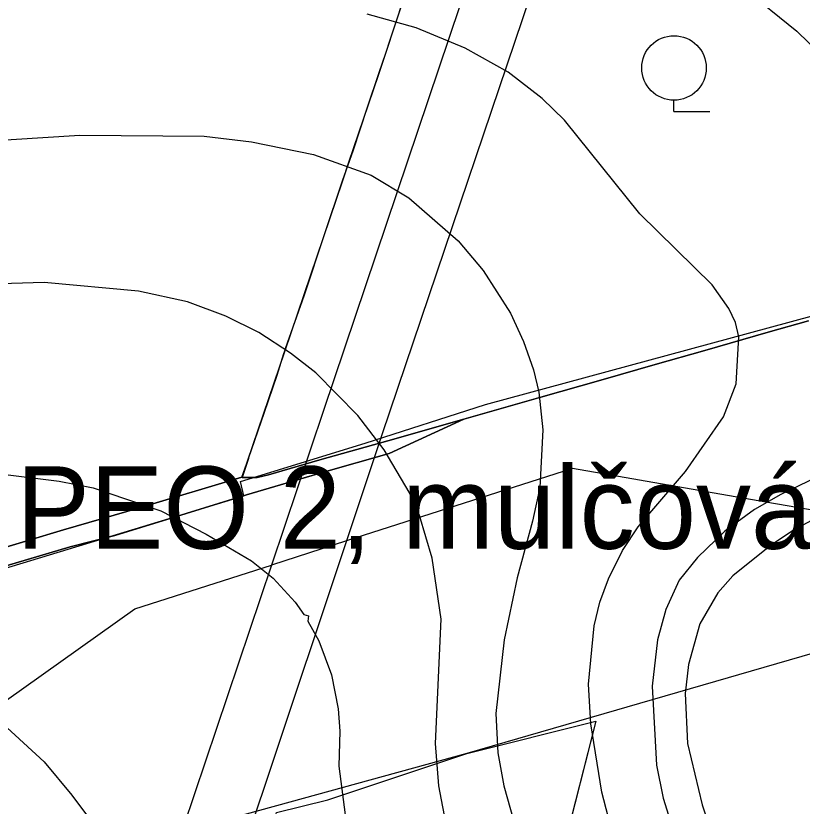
# Model space of a CAD drawing. Extents: x -662620 to -656370, y -1067090 to -1062990.
# Drawn here: x -658244 to -658005.3, y -1065447 to -1065207 of the extents above; entities that cross this region are included whole.
import ezdxf

# ---------------------------------------------------------------- set-up
doc = ezdxf.new("R2010")
doc.units = 0
for name, color, linetype in [('Agrotechnicka_opatreni_hrazkovani_a_dulkovani__mulcovani', 7, 'Continuous'), ('ELEK__VEDENÍ_VN_-_NADZEMNÍ', 7, 'Continuous'), ('ELEK__VEDENÍ_VVN_-_NADZEMNÍ', 7, 'Continuous'), ('OBVOD_PÚ', 7, 'Continuous'), ('ORNÁ_PŮDA_-_STÁVAJÍCÍ', 7, 'Continuous'), ('OSTATNÍ_PLOCHA_-_STÁVAJÍCÍ', 7, 'Continuous'), ('OVOCNÝ_SAD_-_NAVRŽENÝ', 7, 'Continuous'), ('OVOCNÝ_SAD_-_STÁVAJÍCÍ', 7, 'Continuous'), ('OVOCNÝ_SAD_-_ZNAČKA', 7, 'Continuous'), ('VRSTEVNICE_ZDŮRAZNĚNÁ', 7, 'Continuous'), ('VRSTEVNICE_ZÁKLADNÍ', 7, 'Continuous')]:
    doc.layers.add(name, color=color, linetype=linetype)

msp = doc.modelspace()

# ---------------------------------------------------------------- linework, layer by layer
at = {"layer": 'Agrotechnicka_opatreni_hrazkovani_a_dulkovani__mulcovani'}
msp.add_lwpolyline([(-658442.44, -1065523.3), (-658443.3, -1065431.9), (-658351.8, -1065406.5), (-658174.8, -1065352.7), (-658175.8, -1065348.4), (-658137.9, -1065336.7), (-658101.39, -1065325.05), (-657977.61, -1065291.39), (-657955.7, -1065285), (-657886.54, -1065253.17), (-657902.2, -1065289.3), (-657944.34, -1065374.26), (-657952.2, -1065387.5), (-657958.74, -1065388.45), (-657979.2, -1065393.9), (-658107.1, -1065431), (-658344.5, -1065496.2)], close=True, dxfattribs=at)
at = {"layer": 'ELEK__VEDENÍ_VN_-_NADZEMNÍ'}
for points in [[(-657905.04, -1065373.88), (-657939.31, -1065367.86), (-658016.35, -1065354.65), (-658074.98, -1065344.41), (-658143.6, -1065366.43)], [(-658431.73, -1065546.01), (-658402.37, -1065525.35), (-658362.82, -1065497.28), (-658280.56, -1065438.78), (-658207.8, -1065387.04), (-658166.37, -1065373.74)]]:
    msp.add_lwpolyline(points, dxfattribs=at)
at = {"layer": 'ELEK__VEDENÍ_VVN_-_NADZEMNÍ'}
for points in [[(-658053.43, -1065038.07), (-658074.34, -1065100.23), (-658150.55, -1065326.78), (-658166.37, -1065373.74)], [(-658037.26, -1065051.34), (-658078.35, -1065172.84), (-658132.86, -1065334.22), (-658143.6, -1065366.43)], [(-658143.6, -1065366.43), (-658167.84, -1065439.13), (-658202.48, -1065541.95), (-658241.62, -1065658.23), (-658283.03, -1065781.93), (-658282.55, -1065909.7), (-658281.02, -1066039.46), (-658280.08, -1066204), (-658279.27, -1066280.92)], [(-658143.6, -1065366.43), (-658166.37, -1065373.74)], [(-658166.37, -1065373.74), (-658226.48, -1065552.24), (-658303.49, -1065780.98), (-658301.72, -1066029.74), (-658299.99, -1066275.27)]]:
    msp.add_lwpolyline(points, dxfattribs=at)
at = {"layer": 'OBVOD_PÚ'}
for points in [[(-658122.81, -1065191.08), (-658128.25, -1065207.74)], [(-658128.25, -1065207.74), (-658133.86, -1065224.83)], [(-658133.86, -1065224.83), (-658143.06, -1065251.84)], [(-658143.06, -1065251.84), (-658144.85, -1065257.14)], [(-658144.85, -1065257.14), (-658162.41, -1065309.04)], [(-658162.41, -1065309.04), (-658175.32, -1065347.1)], [(-658175.32, -1065347.1), (-658206.44, -1065356.34)], [(-658206.44, -1065356.34), (-658229.45, -1065363.09)], [(-658229.45, -1065363.09), (-658252.46, -1065369.9)]]:
    msp.add_lwpolyline(points, dxfattribs=at)
at = {"layer": 'ORNÁ_PŮDA_-_STÁVAJÍCÍ'}
for p, q in [((-658015.69, -1065303.03), (-658003.41, -1065299.59)), ((-658034.91, -1065308.59), (-658015.69, -1065303.03)), ((-658049.97, -1065312.82), (-658034.91, -1065308.59)), ((-658065.75, -1065317.44), (-658049.97, -1065312.82)), ((-658085.31, -1065323), (-658065.75, -1065317.44)), ((-658107.97, -1065329.48), (-658085.31, -1065323)), ((-658130.7, -1065339.84), (-658107.97, -1065329.48)), ((-658150.63, -1065345.58), (-658130.7, -1065339.84)), ((-658173.96, -1065352.39), (-658150.63, -1065345.58)), ((-658200.78, -1065360.71), (-658173.96, -1065352.39)), ((-658213.95, -1065364.73), (-658200.78, -1065360.71)), ((-658227.45, -1065368.23), (-658213.95, -1065364.73)), ((-658246.87, -1065373.99), (-658227.45, -1065368.23))]:
    msp.add_line(p, q, dxfattribs=at)
msp.add_lwpolyline([(-658246.87, -1065373.99), (-658227.45, -1065368.23), (-658213.95, -1065364.73), (-658200.78, -1065360.71), (-658173.96, -1065352.39), (-658150.63, -1065345.58), (-658130.7, -1065339.84), (-658107.97, -1065329.48), (-658085.31, -1065323), (-658065.75, -1065317.44), (-658049.97, -1065312.82), (-658034.91, -1065308.59), (-658015.69, -1065303.03), (-658003.41, -1065299.59)], dxfattribs=at)
at = {"layer": 'OSTATNÍ_PLOCHA_-_STÁVAJÍCÍ'}
for p, q in [((-658131.1, -1065335.99), (-658107.97, -1065329.48)), ((-658131.1, -1065335.99), (-658107.97, -1065329.48)), ((-658107.97, -1065329.48), (-658130.7, -1065339.84)), ((-658107.97, -1065329.48), (-658130.7, -1065339.84)), ((-658151.72, -1065341.81), (-658131.1, -1065335.99)), ((-658151.72, -1065341.81), (-658131.1, -1065335.99)), ((-658130.7, -1065339.84), (-658150.63, -1065345.58)), ((-658130.7, -1065339.84), (-658150.63, -1065345.58)), ((-658175.32, -1065347.1), (-658173.38, -1065341.37)), ((-658175.32, -1065347.1), (-658173.38, -1065341.37)), ((-658173.37, -1065341.37), (-658175.29, -1065347.12)), ((-658173.37, -1065341.37), (-658175.29, -1065347.12)), ((-658173.38, -1065341.37), (-658173.37, -1065341.37)), ((-658173.38, -1065341.37), (-658173.37, -1065341.37)), ((-658167.27, -1065346.39), (-658151.72, -1065341.81)), ((-658167.27, -1065346.39), (-658151.72, -1065341.81)), ((-658206.44, -1065356.34), (-658175.32, -1065347.1)), ((-658206.44, -1065356.34), (-658175.32, -1065347.1)), ((-658175.29, -1065347.12), (-658170.74, -1065347.17)), ((-658175.29, -1065347.12), (-658170.74, -1065347.17)), ((-658150.63, -1065345.58), (-658173.96, -1065352.39)), ((-658150.63, -1065345.58), (-658173.96, -1065352.39)), ((-658170.74, -1065347.17), (-658167.27, -1065346.39)), ((-658170.74, -1065347.17), (-658167.27, -1065346.39)), ((-658173.96, -1065352.39), (-658200.78, -1065360.71)), ((-658173.96, -1065352.39), (-658200.78, -1065360.71)), ((-658229.45, -1065363.09), (-658206.44, -1065356.34)), ((-658229.45, -1065363.09), (-658206.44, -1065356.34)), ((-658200.78, -1065360.71), (-658213.95, -1065364.73)), ((-658200.78, -1065360.71), (-658213.95, -1065364.73)), ((-658252.46, -1065369.9), (-658229.45, -1065363.09)), ((-658252.46, -1065369.9), (-658229.45, -1065363.09)), ((-658213.95, -1065364.73), (-658227.45, -1065368.23)), ((-658213.95, -1065364.73), (-658227.45, -1065368.23)), ((-658227.45, -1065368.23), (-658246.87, -1065373.99)), ((-658227.45, -1065368.23), (-658246.87, -1065373.99))]:
    msp.add_line(p, q, dxfattribs=at)
msp.add_lwpolyline([(-658252.46, -1065369.9), (-658229.45, -1065363.09), (-658206.44, -1065356.34), (-658175.32, -1065347.1), (-658173.38, -1065341.37), (-658173.37, -1065341.37), (-658175.29, -1065347.12), (-658170.74, -1065347.17), (-658167.27, -1065346.39), (-658151.72, -1065341.81), (-658131.1, -1065335.99), (-658107.97, -1065329.48), (-658130.7, -1065339.84), (-658150.63, -1065345.58), (-658173.96, -1065352.39), (-658200.78, -1065360.71), (-658213.95, -1065364.73), (-658227.45, -1065368.23), (-658246.87, -1065373.99)], dxfattribs=at)
msp.add_lwpolyline([(-658252.46, -1065369.9), (-658229.45, -1065363.09), (-658206.44, -1065356.34), (-658175.32, -1065347.1), (-658173.38, -1065341.37), (-658173.37, -1065341.37), (-658175.29, -1065347.12), (-658170.74, -1065347.17), (-658167.27, -1065346.39), (-658151.72, -1065341.81), (-658131.1, -1065335.99), (-658107.97, -1065329.48), (-658130.7, -1065339.84), (-658150.63, -1065345.58), (-658173.96, -1065352.39), (-658200.78, -1065360.71), (-658213.95, -1065364.73), (-658227.45, -1065368.23), (-658246.87, -1065373.99)], dxfattribs=at)
at = {"layer": 'OVOCNÝ_SAD_-_NAVRŽENÝ'}
for p, q in [((-658107.1, -1065431), (-658067.9, -1065421.1)), ((-658067.9, -1065421.1), (-658088.9, -1065503.2)), ((-658149.3, -1065445), (-658107.1, -1065431)), ((-658164.8, -1065448.9), (-658149.3, -1065445))]:
    msp.add_line(p, q, dxfattribs=at)
msp.add_lwpolyline([(-658221.5, -1065701.5), (-658165.55, -1065451.1), (-658164.91, -1065449.23), (-658164.8, -1065448.9), (-658149.3, -1065445), (-658107.1, -1065431), (-658067.9, -1065421.1), (-658088.9, -1065503.2), (-658064.4, -1065506.7), (-658074.9, -1065548.6), (-658009.6, -1065541.5), (-657999.43, -1065500.58)], dxfattribs=at)
at = {"layer": 'OVOCNÝ_SAD_-_STÁVAJÍCÍ'}
for p, q in [((-658131.66, -1065218.34), (-658126.03, -1065201.07)), ((-658133.65, -1065224.19), (-658131.66, -1065218.34)), ((-658137.14, -1065234.45), (-658133.86, -1065224.83)), ((-658133.86, -1065224.83), (-658133.65, -1065224.19)), ((-658137.22, -1065234.7), (-658137.14, -1065234.45)), ((-658141.47, -1065247.67), (-658137.22, -1065234.7)), ((-658144.86, -1065257.14), (-658141.47, -1065247.67)), ((-658150.17, -1065273.09), (-658144.86, -1065257.14)), ((-658156.33, -1065291.68), (-658150.17, -1065273.09)), ((-658162.07, -1065308.03), (-658156.33, -1065291.68)), ((-658003.41, -1065299.59), (-658015.69, -1065303.03)), ((-658015.69, -1065303.03), (-658034.91, -1065308.59)), ((-658162.41, -1065309.04), (-658162.07, -1065308.03)), ((-658034.91, -1065308.59), (-658049.97, -1065312.82)), ((-658164.63, -1065316.15), (-658162.57, -1065309.52)), ((-658162.57, -1065309.52), (-658162.41, -1065309.04)), ((-658049.97, -1065312.82), (-658065.75, -1065317.44)), ((-658168.53, -1065327.3), (-658164.63, -1065316.15)), ((-658065.75, -1065317.44), (-658085.31, -1065323)), ((-658085.31, -1065323), (-658107.97, -1065329.48)), ((-658173.37, -1065341.37), (-658168.53, -1065327.3)), ((-658107.97, -1065329.48), (-658131.1, -1065335.99)), ((-658131.1, -1065335.99), (-658151.72, -1065341.81)), ((-658175.29, -1065347.12), (-658173.37, -1065341.37)), ((-658151.72, -1065341.81), (-658167.27, -1065346.39)), ((-658170.74, -1065347.17), (-658175.29, -1065347.12)), ((-658167.27, -1065346.39), (-658170.74, -1065347.17))]:
    msp.add_line(p, q, dxfattribs=at)
msp.add_lwpolyline([(-658003.41, -1065299.59), (-658015.69, -1065303.03), (-658034.91, -1065308.59), (-658049.97, -1065312.82), (-658065.75, -1065317.44), (-658085.31, -1065323), (-658107.97, -1065329.48), (-658131.1, -1065335.99), (-658151.72, -1065341.81), (-658167.27, -1065346.39), (-658170.74, -1065347.17), (-658175.29, -1065347.12), (-658173.37, -1065341.37), (-658168.53, -1065327.3), (-658164.63, -1065316.15), (-658162.57, -1065309.52), (-658162.41, -1065309.04), (-658162.07, -1065308.03), (-658156.33, -1065291.68), (-658150.17, -1065273.09), (-658144.86, -1065257.14), (-658141.47, -1065247.67), (-658137.22, -1065234.7), (-658137.14, -1065234.45), (-658133.86, -1065224.83), (-658133.65, -1065224.19), (-658131.66, -1065218.34), (-658126.03, -1065201.07)], dxfattribs=at)
at = {"layer": 'OVOCNÝ_SAD_-_ZNAČKA'}
for points in [[(-658044.22, -1065236.08), (-658044.22, -1065232.62)], [(-658044.22, -1065236.08), (-658033.38, -1065236.08)]]:
    msp.add_lwpolyline(points, dxfattribs=at)
msp.add_circle((-658044.22, -1065222.83), 9.79, dxfattribs=at)
at = {"layer": 'VRSTEVNICE_ZDŮRAZNĚNÁ'}
for points in [[(-658456.04, -1065403.49), (-658411.02, -1065382.05), (-658399.15, -1065377.33), (-658379.14, -1065370.9), (-658333.69, -1065354.6), (-658316.54, -1065350.46), (-658295.1, -1065347.46), (-658247.93, -1065346.17), (-658230.78, -1065348.32), (-658220.49, -1065350.32), (-658199.9, -1065357.32), (-658186.18, -1065364.32), (-658172.46, -1065372.47), (-658165.89, -1065377.76), (-658159.17, -1065385.05), (-658156.6, -1065388.77), (-658155.17, -1065389.19), (-658155.31, -1065390.77), (-658152.02, -1065396.77), (-658148.16, -1065407.06), (-658146.16, -1065417.35), (-658145.59, -1065424.21), (-658145.88, -1065434.79), (-658143.73, -1065451.94)], [(-657980.36, -1065348.32), (-658007.8, -1065363.04), (-658014.66, -1065367.61), (-658026.38, -1065377.05), (-658030.96, -1065382.19), (-658036.39, -1065391.62), (-658039.82, -1065403.92), (-658040.82, -1065412.78), (-658040.1, -1065427.93), (-658035.67, -1065446.51), (-658030.67, -1065461.38), (-658024.53, -1065476.24), (-658013.09, -1065498.54), (-657976.5, -1065554.85)]]:
    msp.add_lwpolyline(points, dxfattribs=at)
at = {"layer": 'VRSTEVNICE_ZÁKLADNÍ'}
for points in [[(-658023.24, -1065198.38), (-658006.94, -1065211.67), (-657995.8, -1065222.53)], [(-658023.24, -1065198.38), (-658006.94, -1065211.67), (-657995.8, -1065222.53)], [(-658060.4, -1065464.81), (-658066.12, -1065442.65), (-658069.41, -1065421.93), (-658070.12, -1065409.92), (-658068.41, -1065392.2), (-658066.69, -1065385.05), (-658064.12, -1065377.9), (-658059.83, -1065369.33), (-658055.11, -1065362.18), (-658040.68, -1065345.31), (-658029.24, -1065328.73), (-658025.38, -1065318.73), (-658024.53, -1065304.44), (-658025.53, -1065300.15), (-658027.53, -1065295.86), (-658032.67, -1065288.71), (-658054.54, -1065267.13), (-658077.41, -1065238.69), (-658084.27, -1065232.11), (-658094.56, -1065224.11), (-658107.57, -1065216.82), (-658122.43, -1065210.67), (-658137.3, -1065206.53)], [(-658060.4, -1065464.81), (-658066.12, -1065442.65), (-658069.41, -1065421.93), (-658070.12, -1065409.92), (-658068.41, -1065392.2), (-658066.69, -1065385.05), (-658064.12, -1065377.9), (-658059.83, -1065369.33), (-658055.11, -1065362.18), (-658040.68, -1065345.31), (-658029.24, -1065328.73), (-658025.38, -1065318.73), (-658024.53, -1065304.44), (-658025.53, -1065300.15), (-658027.53, -1065295.86), (-658032.67, -1065288.71), (-658054.54, -1065267.13), (-658077.41, -1065238.69), (-658084.27, -1065232.11), (-658094.56, -1065224.11), (-658107.57, -1065216.82), (-658122.43, -1065210.67), (-658137.3, -1065206.53)], [(-658283.95, -1065246.98), (-658224.49, -1065243.26), (-658186.75, -1065243.55), (-658172.46, -1065245.26), (-658153.64, -1065249.16), (-658136.16, -1065255.41), (-658124.72, -1065262.27), (-658109.71, -1065275.28), (-658102.14, -1065284.28), (-658093.85, -1065297.29), (-658089.85, -1065305.86), (-658086.84, -1065314.44), (-658085.27, -1065321.3), (-658083.99, -1065332.74), (-658084.98, -1065350.17), (-658087.13, -1065360.47), (-658091.85, -1065377.62), (-658095.71, -1065396.48), (-658098.28, -1065418.78), (-658097.71, -1065430.79), (-658095.85, -1065440.79), (-658091.85, -1065455.09)], [(-658283.95, -1065246.98), (-658224.49, -1065243.26), (-658186.75, -1065243.55), (-658172.46, -1065245.26), (-658153.64, -1065249.16), (-658136.16, -1065255.41), (-658124.72, -1065262.27), (-658109.71, -1065275.28), (-658102.14, -1065284.28), (-658093.85, -1065297.29), (-658089.85, -1065305.86), (-658086.84, -1065314.44), (-658085.27, -1065321.3), (-658083.99, -1065332.74), (-658084.98, -1065350.17), (-658087.13, -1065360.47), (-658091.85, -1065377.62), (-658095.71, -1065396.48), (-658098.28, -1065418.78), (-658097.71, -1065430.79), (-658095.85, -1065440.79), (-658091.85, -1065455.09)], [(-658110.14, -1065469.38), (-658115.57, -1065440.79), (-658116.57, -1065427.93), (-658114.86, -1065390.2), (-658117.57, -1065371.61), (-658121.43, -1065358.75), (-658124.58, -1065351.6), (-658132.15, -1065338.74), (-658140.16, -1065328.31), (-658152.88, -1065315.44), (-658160.6, -1065309.44), (-658170.17, -1065303.15), (-658180.18, -1065298.15), (-658191.9, -1065293.86), (-658206.76, -1065290.57), (-658235.35, -1065288), (-658265.08, -1065288.86), (-658287.95, -1065291.86), (-658303.96, -1065296.43), (-658333.69, -1065308.44), (-658361.13, -1065318.16), (-658396.29, -1065329.16), (-658477.76, -1065352.46)], [(-658110.14, -1065469.38), (-658115.57, -1065440.79), (-658116.57, -1065427.93), (-658114.86, -1065390.2), (-658117.57, -1065371.61), (-658121.43, -1065358.75), (-658124.58, -1065351.6), (-658132.15, -1065338.74), (-658140.16, -1065328.31), (-658152.88, -1065315.44), (-658160.6, -1065309.44), (-658170.17, -1065303.15), (-658180.18, -1065298.15), (-658191.9, -1065293.86), (-658206.76, -1065290.57), (-658235.35, -1065288), (-658265.08, -1065288.86), (-658287.95, -1065291.86), (-658303.96, -1065296.43), (-658333.69, -1065308.44), (-658361.13, -1065318.16), (-658396.29, -1065329.16), (-658477.76, -1065352.46)], [(-657989.79, -1065341.74), (-658011.8, -1065352.32), (-658019.81, -1065356.89), (-658028.81, -1065363.47), (-658037.1, -1065371.47), (-658042.68, -1065378.33), (-658046.68, -1065387.19), (-658049.25, -1065396.48), (-658050.82, -1065410.49), (-658049.54, -1065434.5), (-658047.54, -1065444.51), (-658041.25, -1065464.52), (-658035.53, -1065478.53), (-658005.23, -1065539.7)], [(-657989.79, -1065341.74), (-658011.8, -1065352.32), (-658019.81, -1065356.89), (-658028.81, -1065363.47), (-658037.1, -1065371.47), (-658042.68, -1065378.33), (-658046.68, -1065387.19), (-658049.25, -1065396.48), (-658050.82, -1065410.49), (-658049.54, -1065434.5), (-658047.54, -1065444.51), (-658041.25, -1065464.52), (-658035.53, -1065478.53), (-658005.23, -1065539.7)], [(-658451.75, -1065447.37), (-658425.17, -1065436.36), (-658367.42, -1065415.35), (-658351.41, -1065411.06), (-658339.41, -1065408.92), (-658329.4, -1065408.06), (-658302.53, -1065408.49), (-658268.51, -1065413.35), (-658258.22, -1065415.92), (-658247.93, -1065421.93), (-658235.35, -1065433.5), (-658226.92, -1065443.65), (-658213.34, -1065461.95), (-658197.9, -1065486.53), (-658193.47, -1065495.11), (-658188.76, -1065506.54), (-658182.18, -1065527.98), (-658177.46, -1065552.28), (-658173.18, -1065590.87), (-658172.32, -1065603.74), (-658172.32, -1065619.46), (-658173.46, -1065638.04), (-658177.61, -1065666.63), (-658184.75, -1065698.07)], [(-658451.75, -1065447.37), (-658425.17, -1065436.36), (-658367.42, -1065415.35), (-658351.41, -1065411.06), (-658339.41, -1065408.92), (-658329.4, -1065408.06), (-658302.53, -1065408.49), (-658268.51, -1065413.35), (-658258.22, -1065415.92), (-658247.93, -1065421.93), (-658235.35, -1065433.5), (-658226.92, -1065443.65), (-658213.34, -1065461.95), (-658197.9, -1065486.53), (-658193.47, -1065495.11), (-658188.76, -1065506.54), (-658182.18, -1065527.98), (-658177.46, -1065552.28), (-658173.18, -1065590.87), (-658172.32, -1065603.74), (-658172.32, -1065619.46), (-658173.46, -1065638.04), (-658177.61, -1065666.63), (-658184.75, -1065698.07)]]:
    msp.add_lwpolyline(points, dxfattribs=at)

# ---------------------------------------------------------------- texts
at = {"layer": 'Agrotechnicka_opatreni_hrazkovani_a_dulkovani__mulcovani'}
msp.add_text('PEO 2, mulčování', height=25, dxfattribs=at).set_placement((-658243.78, -1065368.8))

doc.saveas('drawing.dxf')
